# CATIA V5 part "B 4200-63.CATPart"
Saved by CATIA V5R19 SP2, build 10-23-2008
Part number: B 4200-63
Bounding box of the stored display mesh (mm): x -47.487 to 47.487, y -47.487 to 47.487, z 0 to 247
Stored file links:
  C:\Users\Bora\Desktop\3D Katı model\B serisi\B 4200\B 4200-63.CATPart
  C:\Program Files\Dassault Systemes\B19\intel_a\reffiles\standard\MetricThickPitch.txt
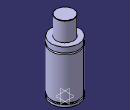
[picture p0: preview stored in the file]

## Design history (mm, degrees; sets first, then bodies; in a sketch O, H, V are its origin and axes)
Body1 (main body)
  Sketch1 on yz-plane, origin (0, 0, 0), H (0, 1, 0), V (0, 0, 1)
    point P1 (47.5, 162.5)
    point P2 (47.5, 157.5)
    point P3 (47.5, 162.5)
    point P6 (47.5, 157.5)
    point P9 (30, 246)
    point P11 (30, 246)
    arc A1 centre (47.5, 160) radius 2.5 from (47.5, 162.5) to (47.5, 157.5) ccw
    line L1 (47.5, 162.5) -> (47.5, 181)
    line L2 (47.5, 13) -> (47.5, 157.5)
    line L3 (43.5, 13) -> (43.5, 8)
    arc A2 centre (29, 246) radius 1 from (30, 246) to (29, 247) ccw
    line L4 (30, 246) -> (30, 181)
    line L5 (47.5, 0) -> (47.5, 8)
    line L6 (29, 247) -> (0, 247)
    point P15 (0, 247)
    line L7 (30, 181) -> (47.5, 181)
    line L8 (0, 0) -> (47.5, 0)
    line L9 (43.5, 8) -> (47.5, 8)
    line L10 (43.5, 13) -> (47.5, 13)
    coincidence: P15 V, P1 P3, P2 P6, P9 P11
    tangency: L6 A2
    horizontal: L7 H, L8 H, L9 H, L10 H
  Shaft1: profile Sketch1, axis Sketch1.V, angle 360
  Sketch2 on face of Shaft1 from Sketch1.L8, origin (0, 0, 0), H (1, 0, 0), V (0, -1, 0)
    point P1 (30, 0)
    distance P1 V = 30
  Hole1: placed by Sketch2, at (30, 0, 0) direction (0, 0, 1), diameter 6.647, depth 13, threaded "M8", thread diameter 8, thread depth 13, pitch 1.25
  CircPattern1: of Hole1, instances 4, angular step 90, axis from xy-plane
